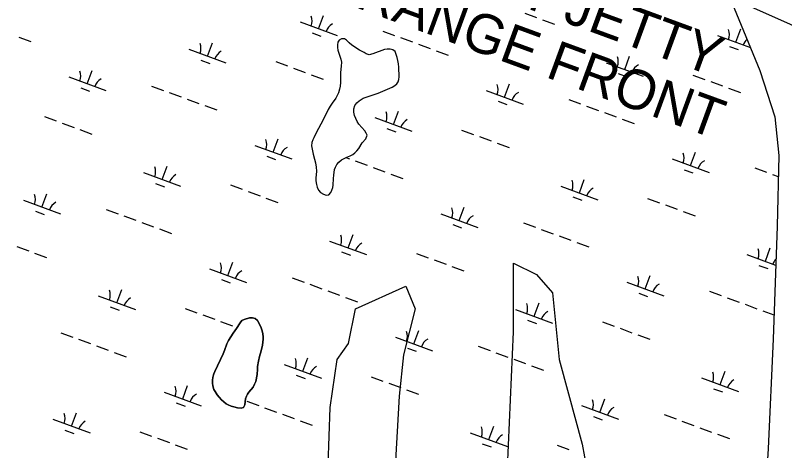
# Model space of a CAD drawing. Extents: x 3972907 to 3994831, y 172639 to 190852.
# Drawn here: x 3981218 to 3982193, y 184468 to 185019 of the extents above; entities that cross this region are included whole.
import ezdxf

# ---------------------------------------------------------------- set-up
doc = ezdxf.new("R2010")
doc.units = 0
for name, color, linetype in [('V-CHAN-NAID', 7, 'Continuous'), ('V-RIVR-JETY', 7, 'Continuous'), ('V-RIVR-RANG', 7, 'Continuous'), ('V-SITE-VEGE', 7, 'Continuous'), ('V-TOPO-SHOR', 7, 'Continuous'), ('V-WETL-SWMP', 7, 'Continuous')]:
    doc.layers.add(name, color=color, linetype=linetype)

msp = doc.modelspace()

# ---------------------------------------------------------------- linework, layer by layer
at = {"layer": 'V-RIVR-JETY'}
msp.add_spline([(3980663.75, 188142.49), (3980923.3, 187897.84), (3981219.12, 187593.73), (3981381.55, 187411.23), (3981548.76, 187223.47), (3981745.95, 186997.4), (3981995.88, 186703.14), (3982287.95, 186350.33), (3982495.82, 186079.54), (3982762.84, 185654.69), (3982971.02, 185292.43), (3983111.24, 185037.47), (3983200.02, 184881.79), (3983229.93, 184826.38)], degree=3, dxfattribs=at)
at = {"layer": 'V-RIVR-RANG'}
msp.add_lwpolyline([(3982021.28, 185087.72), (3990774.16, 181190.72)], dxfattribs=at)
at = {"layer": 'V-SITE-VEGE'}
for points in [[(3981878.15, 183971.42), (3981872.35, 184043.96), (3981854.95, 184183.23), (3981843.35, 184267.38), (3981837.55, 184360.22), (3981849.15, 184618.46), (3981849.15, 184705.5), (3981878.15, 184691), (3981898.45, 184667.78), (3981907.15, 184583.64), (3981918.75, 184540.12), (3981936.15, 184476.28), (3981947.75, 184412.45), (3981959.35, 184357.32), (3981973.85, 184310.9), (3981988.35, 184261.57), (3981982.55, 184252.87), (3981970.95, 184235.46), (3981965.15, 184206.44), (3981976.75, 184133.9), (3982005.75, 184078.78), (3982046.35, 184017.85)], [(3981518.56, 183893.08), (3981538.87, 184133.9), (3981562.06, 184229.65), (3981582.36, 184270.27), (3981602.66, 184325.4), (3981608.46, 184366.02), (3981614.26, 184450.17), (3981617.16, 184522.71), (3981625.86, 184583.64), (3981640.36, 184603.95), (3981649.06, 184647.47), (3981712.86, 184676.49), (3981724.46, 184647.47), (3981709.96, 184589.44), (3981704.16, 184537.22), (3981698.36, 184432.76), (3981704.16, 184345.71), (3981672.26, 184281.88), (3981663.56, 184189.03), (3981680.96, 184067.17), (3981672.26, 183948.21)]]:
    msp.add_lwpolyline(points, dxfattribs=at)
at = {"layer": 'V-TOPO-SHOR'}
msp.add_line((3981702.62, 184961.83), (3981701.66, 184965.75), dxfattribs=at)
for points in [[(3981701.66, 184965.75), (3981700.66, 184969.46), (3981699.12, 184973.17), (3981696.26, 184975.34), (3981692.97, 184976.4), (3981689.31, 184976.45), (3981685.92, 184975.82), (3981671.09, 184970.2), (3981666.37, 184969.24), (3981662.72, 184970.4), (3981660.07, 184972.05), (3981654.29, 184974.8), (3981644.28, 184981.31), (3981641.1, 184984.12), (3981637.71, 184987.57), (3981635, 184989.42), (3981631.35, 184989.52), (3981628.43, 184987.83), (3981626.74, 184985.02), (3981626.21, 184981.89), (3981626.16, 184978.34), (3981626.69, 184975), (3981630.29, 184963.77), (3981631.2, 184959.69), (3981631.04, 184954.77), (3981630.19, 184946.66), (3981630.03, 184943.64), (3981629.93, 184934.1), (3981629.51, 184929.33), (3981628.98, 184925.46), (3981627.55, 184921.18), (3981625.86, 184917.62), (3981623.95, 184914.45), (3981619.45, 184907.93), (3981617.01, 184904.11), (3981614.57, 184899.93), (3981607.58, 184885.78), (3981599.75, 184871.31), (3981596.14, 184864.26), (3981594.82, 184861.4), (3981593.76, 184858.12), (3981593.5, 184853.72), (3981595.41, 184843.33), (3981597.21, 184837.14), (3981598.27, 184832.31), (3981599.12, 184826.8), (3981599.49, 184821.72), (3981598.81, 184812.92), (3981598.91, 184809.53), (3981599.5, 184805.08), (3981600.4, 184801.48), (3981602.1, 184797.72), (3981604.58, 184795.07), (3981608.35, 184792.74), (3981611.95, 184791.63), (3981615.18, 184791.89), (3981617.94, 184794.91), (3981619.21, 184797.99), (3981620.27, 184801.11), (3981620.74, 184804.29), (3981621.11, 184812.61), (3981621.48, 184816.8), (3981622.59, 184823.9), (3981623.6, 184827.08), (3981625.35, 184830.36), (3981628, 184833.43), (3981631.23, 184836.03), (3981634.83, 184838.1), (3981637.9, 184839.53), (3981642.35, 184841.28), (3981645.48, 184843.03), (3981648.28, 184845.1), (3981650.93, 184847.75), (3981653.1, 184850.66), (3981657.55, 184857.87), (3981662.16, 184862.9), (3981663.7, 184867.25), (3981662.53, 184870.11), (3981660.73, 184872.97), (3981653.26, 184881.44), (3981651.03, 184884.83), (3981649.39, 184888.49), (3981647.85, 184892.52), (3981646.84, 184896.6), (3981646.84, 184900.57), (3981648.27, 184904.91), (3981650.92, 184908.52), (3981653.51, 184910.85), (3981656.06, 184912.7), (3981658.76, 184914.14), (3981677.62, 184920.71), (3981692.35, 184926.75), (3981695.63, 184928.29), (3981698.97, 184930.15), (3981701.35, 184932.53), (3981703.1, 184935.07), (3981704, 184938.04), (3981704.37, 184941.38), (3981703.73, 184953.46), (3981703.31, 184957.59), (3981702.62, 184961.83)], [(3981522.89, 184555.56), (3981521.2, 184552.39), (3981519.39, 184548.41), (3981514.1, 184542.37), (3981512.46, 184539.83), (3981511.03, 184537.02), (3981509.86, 184533.95), (3981509.12, 184530.02), (3981508.7, 184526.05), (3981507.32, 184522.98), (3981504.41, 184522.13), (3981499.53, 184522.44), (3981494.92, 184523.61), (3981491.74, 184524.61), (3981487.93, 184526.15), (3981485.17, 184527.58), (3981479.29, 184532.4), (3981476.27, 184535.68), (3981473.67, 184538.97), (3981471.13, 184542.83), (3981469.59, 184545.7), (3981468.27, 184550.36), (3981467.79, 184553.75), (3981467.79, 184557.19), (3981468.37, 184560.95), (3981469.59, 184565.41), (3981470.81, 184568.48), (3981481.34, 184590.73), (3981483.09, 184595.03), (3981486.06, 184603.29), (3981488.02, 184607.53), (3981494, 184616.7), (3981496.17, 184619.83), (3981498.5, 184622.79), (3981503.06, 184629.9), (3981505.23, 184632.81), (3981507.98, 184634.14), (3981514.92, 184636.1), (3981518.58, 184636.26), (3981522.13, 184635.3), (3981524.83, 184633.08), (3981527.91, 184627.52), (3981529.39, 184623.81), (3981530.82, 184619.78), (3981531.88, 184616.18), (3981532.31, 184612.1), (3981532.2, 184609.08), (3981531.78, 184605.58), (3981531.09, 184601.87), (3981529.4, 184594.46), (3981527.39, 184587.46), (3981526.12, 184581.32), (3981525.11, 184574.64), (3981524.85, 184571.41), (3981524.64, 184564.52), (3981522.89, 184555.56)]]:
    msp.add_lwpolyline(points, dxfattribs=at)
at = {"layer": 'V-WETL-SWMP'}
for p, q in [((3981602.32, 185002.04), (3981608.53, 185018.94)), ((3981863.42, 185021.8), (3981878.43, 185016.28)), ((3981578.85, 185010.67), (3981625.78, 184993.42)), ((3981885.94, 185013.52), (3981900.96, 185008)), ((3981683.62, 184999.19), (3981698.64, 184993.67)), ((3982130.8, 184985.02), (3982137.01, 185001.91)), ((3981222.72, 184991.38), (3981237.74, 184985.86)), ((3981594.03, 184996.87), (3981605.29, 184992.73)), ((3981706.15, 184990.91), (3981721.17, 184985.39)), ((3982107.33, 184993.64), (3982149.25, 184978.24)), ((3981461.54, 184967.56), (3981467.75, 184984.46)), ((3981728.68, 184982.63), (3981743.69, 184977.11)), ((3982122.5, 184979.85), (3982133.77, 184975.71)), ((3981438.08, 184976.19), (3981485.01, 184958.94)), ((3981751.2, 184974.35), (3981766.22, 184968.83)), ((3981453.25, 184962.39), (3981464.51, 184958.25)), ((3981547.96, 184960.53), (3981562.97, 184955.01)), ((3981990.02, 184950.54), (3981996.23, 184967.43)), ((3981570.48, 184952.25), (3981585.5, 184946.73)), ((3981966.56, 184959.16), (3982013.49, 184941.91)), ((3981285.92, 184941.12), (3981332.85, 184923.87)), ((3981309.39, 184932.49), (3981315.6, 184949.39)), ((3981593.01, 184943.97), (3981608.03, 184938.45)), ((3981981.73, 184945.36), (3981992.99, 184941.22)), ((3982076.44, 184943.51), (3982091.45, 184937.99)), ((3981837.87, 184915.47), (3981844.08, 184932.36)), ((3982098.96, 184935.23), (3982113.98, 184929.71)), ((3981301.09, 184927.32), (3981312.36, 184923.18)), ((3981390.69, 184929.64), (3981405.71, 184924.12)), ((3981413.22, 184921.36), (3981428.24, 184915.84)), ((3981814.4, 184924.09), (3981861.33, 184906.84)), ((3982121.49, 184926.95), (3982136.51, 184921.43)), ((3981435.74, 184913.08), (3981450.76, 184907.56)), ((3981919.17, 184912.62), (3981934.19, 184907.1)), ((3981458.27, 184904.8), (3981473.29, 184899.28)), ((3981829.57, 184910.3), (3981840.84, 184906.16)), ((3981941.7, 184904.34), (3981956.71, 184898.82)), ((3981697.09, 184880.99), (3981703.3, 184897.88)), ((3981964.22, 184896.06), (3981979.24, 184890.54)), ((3981255.03, 184890.98), (3981270.04, 184885.46)), ((3981277.55, 184882.7), (3981292.57, 184877.18)), ((3981673.63, 184889.61), (3981720.56, 184872.36)), ((3981986.75, 184887.78), (3982001.77, 184882.26)), ((3981300.08, 184874.42), (3981315.1, 184868.9)), ((3981688.8, 184875.81), (3981700.06, 184871.67)), ((3981783.5, 184873.96), (3981798.52, 184868.44)), ((3981544.94, 184845.92), (3981551.14, 184862.81)), ((3981806.03, 184865.68), (3981821.05, 184860.16)), ((3981521.47, 184854.54), (3981568.4, 184837.29)), ((3981828.56, 184857.4), (3981843.58, 184851.88)), ((3982073.41, 184828.89), (3982079.62, 184845.79)), ((3981536.64, 184840.75), (3981547.91, 184836.61)), ((3981637, 184839.11), (3981641.26, 184837.55)), ((3981648.76, 184834.79), (3981663.78, 184829.27)), ((3982049.95, 184837.52), (3982096.88, 184820.27)), ((3981404.16, 184811.44), (3981410.37, 184828.33)), ((3981671.29, 184826.51), (3981686.31, 184820.99)), ((3982065.12, 184823.72), (3982076.38, 184819.58)), ((3982154.72, 184826.04), (3982169.73, 184820.52)), ((3981380.7, 184820.06), (3981427.63, 184802.81)), ((3981693.82, 184818.23), (3981708.84, 184812.71)), ((3982177.24, 184817.76), (3982184.35, 184815.15)), ((3981395.87, 184806.26), (3981407.13, 184802.12)), ((3981490.57, 184804.41), (3981505.59, 184798.89)), ((3981932.64, 184794.41), (3981938.85, 184811.3)), ((3981513.1, 184796.13), (3981528.12, 184790.61)), ((3981909.17, 184803.03), (3981956.1, 184785.79)), ((3981228.54, 184784.99), (3981275.47, 184767.74)), ((3981252, 184776.37), (3981258.21, 184793.26)), ((3981535.63, 184787.85), (3981550.64, 184782.33)), ((3981924.35, 184789.24), (3981935.61, 184785.1)), ((3982019.05, 184787.38), (3982034.07, 184781.86)), ((3981780.48, 184759.34), (3981786.69, 184776.24)), ((3982041.58, 184779.1), (3982056.6, 184773.58)), ((3981243.71, 184771.2), (3981254.97, 184767.06)), ((3981333.31, 184773.52), (3981348.32, 184768)), ((3981355.83, 184765.24), (3981370.85, 184759.72)), ((3981757.02, 184767.97), (3981803.95, 184750.72)), ((3982064.11, 184770.82), (3982079.12, 184765.3)), ((3981378.36, 184756.96), (3981393.38, 184751.44)), ((3981861.79, 184756.49), (3981876.8, 184750.97)), ((3981400.89, 184748.68), (3981415.9, 184743.16)), ((3981772.19, 184754.17), (3981783.45, 184750.03)), ((3981884.31, 184748.21), (3981899.33, 184742.69)), ((3981639.71, 184724.86), (3981645.92, 184741.75)), ((3981906.84, 184739.93), (3981921.86, 184734.41)), ((3981220.17, 184726.58), (3981235.19, 184721.06)), ((3981616.24, 184733.48), (3981663.17, 184716.24)), ((3981929.37, 184731.65), (3981944.38, 184726.13)), ((3981242.69, 184718.3), (3981257.71, 184712.78)), ((3981631.41, 184719.69), (3981642.68, 184715.55)), ((3981726.12, 184717.83), (3981741.14, 184712.31)), ((3982144.72, 184716.46), (3982181.14, 184703.07)), ((3982168.19, 184707.83), (3982174.4, 184724.73)), ((3981487.55, 184689.79), (3981493.76, 184706.69)), ((3981748.65, 184709.55), (3981763.67, 184704.03)), ((3981464.09, 184698.42), (3981511.02, 184681.17)), ((3981771.17, 184701.27), (3981786.19, 184695.75)), ((3982159.89, 184702.66), (3982171.16, 184698.52)), ((3981568.85, 184686.94), (3981583.87, 184681.42)), ((3982016.03, 184672.77), (3982022.24, 184689.66)), ((3981479.26, 184684.62), (3981490.52, 184680.48)), ((3981591.38, 184678.66), (3981606.4, 184673.14)), ((3981992.56, 184681.39), (3982039.5, 184664.14)), ((3981346.78, 184655.31), (3981352.99, 184672.2)), ((3981613.91, 184670.38), (3981628.93, 184664.86)), ((3982007.74, 184667.6), (3982019, 184663.46)), ((3982097.33, 184669.91), (3982112.35, 184664.39)), ((3981323.31, 184663.93), (3981370.24, 184646.68)), ((3981636.43, 184662.1), (3981651.45, 184656.58)), ((3982119.86, 184661.63), (3982134.88, 184656.12)), ((3981338.48, 184650.14), (3981349.75, 184646)), ((3981433.19, 184648.28), (3981448.21, 184642.76)), ((3981875.26, 184638.28), (3981881.47, 184655.18)), ((3982142.39, 184653.36), (3982157.4, 184647.84)), ((3981455.72, 184640), (3981470.73, 184634.48)), ((3981851.79, 184646.91), (3981898.72, 184629.66)), ((3982164.91, 184645.08), (3982178.9, 184639.93)), ((3981478.24, 184631.72), (3981493.26, 184626.2)), ((3981866.96, 184633.11), (3981878.23, 184628.97)), ((3981961.67, 184631.26), (3981976.69, 184625.74)), ((3981723.1, 184603.22), (3981729.31, 184620.11)), ((3981984.19, 184622.98), (3981999.21, 184617.46)), ((3981275.92, 184617.39), (3981290.94, 184611.87)), ((3981298.45, 184609.11), (3981313.47, 184603.59)), ((3981699.63, 184611.84), (3981746.56, 184594.59)), ((3982006.72, 184614.7), (3982021.74, 184609.18)), ((3981320.98, 184600.83), (3981335.99, 184595.31)), ((3981804.4, 184600.36), (3981819.42, 184594.84)), ((3981343.5, 184592.55), (3981358.52, 184587.03)), ((3981714.81, 184598.04), (3981726.07, 184593.91)), ((3981826.93, 184592.08), (3981841.95, 184586.56)), ((3981582.32, 184568.73), (3981588.53, 184585.63)), ((3981849.46, 184583.8), (3981864.47, 184578.29)), ((3981558.86, 184577.36), (3981605.79, 184560.11)), ((3981871.98, 184575.53), (3981887, 184570.01)), ((3981574.03, 184563.56), (3981585.29, 184559.42)), ((3981668.74, 184561.71), (3981683.75, 184556.19)), ((3982087.34, 184560.33), (3982134.27, 184543.08)), ((3982110.8, 184551.71), (3982117.01, 184568.6)), ((3981430.17, 184533.67), (3981436.38, 184550.56)), ((3981691.26, 184553.43), (3981706.28, 184547.91)), ((3981406.7, 184542.29), (3981453.63, 184525.04)), ((3981713.79, 184545.15), (3981728.81, 184539.63)), ((3982102.51, 184546.54), (3982113.77, 184542.4)), ((3981958.65, 184516.64), (3981964.86, 184533.54)), ((3981421.87, 184528.49), (3981433.14, 184524.35)), ((3981511.47, 184530.81), (3981526.49, 184525.29)), ((3981534, 184522.53), (3981549.01, 184517.01)), ((3981935.18, 184525.27), (3981982.11, 184508.02)), ((3981289.39, 184499.18), (3981295.6, 184516.08)), ((3981556.52, 184514.25), (3981571.54, 184508.73)), ((3981950.35, 184511.47), (3981961.62, 184507.33)), ((3982039.95, 184513.79), (3982054.97, 184508.27)), ((3981265.93, 184507.81), (3981312.86, 184490.56)), ((3981579.05, 184505.98), (3981594.07, 184500.46)), ((3982062.48, 184505.51), (3982077.49, 184499.99)), ((3981281.1, 184494.01), (3981292.36, 184489.87)), ((3981375.81, 184492.16), (3981390.82, 184486.64)), ((3981817.87, 184482.16), (3981824.08, 184499.05)), ((3982085, 184497.23), (3982100.02, 184491.71)), ((3981398.33, 184483.88), (3981413.35, 184478.36)), ((3981794.41, 184490.78), (3981841.34, 184473.53)), ((3982107.53, 184488.95), (3982122.55, 184483.43)), ((3981420.86, 184475.6), (3981435.88, 184470.08)), ((3981809.58, 184476.99), (3981820.84, 184472.85)), ((3981904.28, 184475.13), (3981919.3, 184469.61))]:
    msp.add_line(p, q, dxfattribs=at)
for points in [[(3981942.39, 185380.79), (3982015.33, 185252.38), (3982074.7, 185148.97), (3982125.59, 185035.39), (3982161.21, 184949.36), (3982180.3, 184890.44), (3982184.98, 184841.7), (3982182.88, 184752.27), (3982177.83, 184609.42), (3982171.5, 184470.82), (3982161.79, 184311.87), (3982156.74, 184185.55), (3982155.91, 184088.07), (3982163.13, 184030)], [(3981701.66, 184965.75), (3981700.65, 184969.46), (3981699.12, 184973.17), (3981696.25, 184975.34), (3981692.97, 184976.4), (3981689.31, 184976.45), (3981685.92, 184975.82), (3981671.09, 184970.2), (3981666.37, 184969.24), (3981662.72, 184970.4), (3981660.07, 184972.05), (3981654.29, 184974.8), (3981644.28, 184981.32), (3981641.1, 184984.12), (3981637.71, 184987.57), (3981635, 184989.42), (3981631.35, 184989.52), (3981628.43, 184987.83), (3981626.74, 184985.02), (3981626.21, 184981.89), (3981626.16, 184978.34), (3981626.69, 184975.01), (3981630.29, 184963.77), (3981631.2, 184959.69), (3981631.04, 184954.77), (3981630.19, 184946.66), (3981630.03, 184943.64), (3981629.93, 184934.1), (3981629.51, 184929.33), (3981628.98, 184925.47), (3981627.55, 184921.17), (3981625.85, 184917.62), (3981623.95, 184914.45), (3981619.45, 184907.93), (3981617.01, 184904.11), (3981614.57, 184899.93), (3981607.58, 184885.78), (3981599.75, 184871.31), (3981596.14, 184864.26), (3981594.82, 184861.4), (3981593.76, 184858.12), (3981593.5, 184853.72), (3981595.41, 184843.33), (3981597.21, 184837.14), (3981598.27, 184832.31), (3981599.12, 184826.8), (3981599.49, 184821.72), (3981598.81, 184812.92), (3981598.91, 184809.53), (3981599.5, 184805.08), (3981600.4, 184801.48), (3981602.09, 184797.72), (3981604.58, 184795.07), (3981608.35, 184792.74), (3981611.95, 184791.63), (3981615.18, 184791.89), (3981617.94, 184794.91), (3981619.21, 184797.99), (3981620.27, 184801.11), (3981620.74, 184804.29), (3981621.11, 184812.61), (3981621.48, 184816.8), (3981622.59, 184823.9), (3981623.6, 184827.08), (3981625.35, 184830.36), (3981628, 184833.43), (3981631.23, 184836.03), (3981634.83, 184838.1), (3981637.9, 184839.53), (3981642.35, 184841.28), (3981645.48, 184843.03), (3981648.28, 184845.1), (3981650.93, 184847.74), (3981653.1, 184850.66), (3981657.55, 184857.87), (3981662.16, 184862.9), (3981663.7, 184867.25), (3981662.53, 184870.11), (3981660.73, 184872.97), (3981653.26, 184881.44), (3981651.03, 184884.83), (3981649.39, 184888.49), (3981647.85, 184892.52), (3981646.84, 184896.6), (3981646.84, 184900.57), (3981648.27, 184904.91), (3981650.92, 184908.52), (3981653.51, 184910.85), (3981656.06, 184912.7), (3981658.76, 184914.14), (3981677.62, 184920.71), (3981692.35, 184926.75), (3981695.63, 184928.29), (3981698.97, 184930.15), (3981701.35, 184932.53), (3981703.1, 184935.08), (3981704, 184938.04), (3981704.37, 184941.38), (3981703.73, 184953.46)], [(3981703.73, 184953.46), (3981703.31, 184957.59), (3981702.62, 184961.83), (3981701.66, 184965.75)]]:
    msp.add_lwpolyline(points, dxfattribs=at)
msp.add_lwpolyline([(3981522.89, 184555.56), (3981524.64, 184564.52), (3981524.85, 184571.41), (3981525.11, 184574.64), (3981526.12, 184581.32), (3981527.39, 184587.46), (3981529.4, 184594.46), (3981531.09, 184601.87), (3981531.78, 184605.58), (3981532.2, 184609.08), (3981532.31, 184612.1), (3981531.88, 184616.18), (3981530.82, 184619.78), (3981529.39, 184623.81), (3981527.91, 184627.52), (3981524.83, 184633.08), (3981522.13, 184635.3), (3981518.58, 184636.26), (3981514.92, 184636.1), (3981507.98, 184634.14), (3981505.23, 184632.81), (3981503.06, 184629.89), (3981498.5, 184622.79), (3981496.17, 184619.83), (3981494, 184616.7), (3981488.02, 184607.53), (3981486.06, 184603.29), (3981483.09, 184595.03), (3981481.34, 184590.74), (3981470.81, 184568.48), (3981469.59, 184565.41), (3981468.37, 184560.96), (3981467.79, 184557.19), (3981467.79, 184553.75), (3981468.27, 184550.36), (3981469.59, 184545.7), (3981471.13, 184542.84), (3981473.67, 184538.97), (3981476.27, 184535.68), (3981479.29, 184532.4), (3981485.17, 184527.58), (3981487.93, 184526.15), (3981491.74, 184524.61), (3981494.92, 184523.61), (3981499.53, 184522.44), (3981504.41, 184522.13), (3981507.32, 184522.98), (3981508.7, 184526.05), (3981509.12, 184530.02), (3981509.86, 184533.94), (3981511.03, 184537.02), (3981512.46, 184539.83), (3981514.1, 184542.37), (3981519.4, 184548.41), (3981521.2, 184552.39)], close=True, dxfattribs=at)
for centre, start, end in [((3981576.48, 185011.8), 339.04728, 20.59094), ((3981628.33, 184992.74), 119.04728, 160.59093), ((3982104.95, 184994.77), 339.04728, 20.59094), ((3982156.81, 184975.71), 132.44085, 160.59093), ((3981435.7, 184977.31), 339.04728, 20.59094), ((3981487.55, 184958.25), 119.04728, 160.59093), ((3981964.18, 184960.29), 339.04728, 20.59094), ((3982016.03, 184941.23), 119.04728, 160.59093), ((3981283.54, 184942.25), 339.04728, 20.59094), ((3981335.4, 184923.19), 119.04728, 160.59093), ((3981812.02, 184925.22), 339.04728, 20.59094), ((3981863.87, 184906.16), 119.04728, 160.59093), ((3981671.25, 184890.74), 339.04728, 20.59094), ((3981723.1, 184871.68), 119.04728, 160.59093), ((3981519.09, 184855.67), 339.04728, 20.59094), ((3981570.94, 184836.61), 119.04728, 160.59093), ((3982047.57, 184838.64), 339.04728, 20.59094), ((3982099.42, 184819.59), 119.04728, 160.59093), ((3981378.32, 184821.19), 339.04728, 20.59094), ((3981430.17, 184802.13), 119.04728, 160.59093), ((3981906.8, 184804.16), 339.04728, 20.59094), ((3981958.65, 184785.1), 119.04728, 160.59093), ((3981226.16, 184786.12), 339.04728, 20.59094), ((3981278.01, 184767.06), 119.04728, 160.59093), ((3981754.64, 184769.09), 339.04728, 20.59094), ((3981806.49, 184750.04), 119.04728, 160.59093), ((3981613.86, 184734.61), 339.04728, 20.59094), ((3981665.72, 184715.55), 119.04728, 160.59093), ((3982142.34, 184717.59), 339.04728, 20.59094), ((3982194.19, 184698.53), 136.52653, 160.59093), ((3981461.71, 184699.54), 339.04728, 20.59094), ((3981513.56, 184680.49), 119.04728, 160.59093), ((3981990.19, 184682.52), 339.04728, 20.59094), ((3982042.04, 184663.46), 119.04728, 160.59093), ((3981320.93, 184665.06), 339.04728, 20.59094), ((3981372.78, 184646), 119.04728, 160.59093), ((3981849.41, 184648.04), 339.04728, 20.59094), ((3981901.26, 184628.98), 119.04728, 160.59093), ((3981697.25, 184612.97), 339.04728, 20.59094), ((3981749.11, 184593.91), 119.04728, 160.59093), ((3981556.48, 184578.49), 339.04728, 20.59094), ((3981608.33, 184559.43), 119.04728, 160.59093), ((3982084.96, 184561.46), 339.04728, 20.59094), ((3982136.81, 184542.4), 119.04728, 160.59093), ((3981404.32, 184543.42), 339.04728, 20.59094), ((3981456.17, 184524.36), 119.04728, 160.59093), ((3981932.8, 184526.39), 339.04728, 20.59094), ((3981984.65, 184507.34), 119.04728, 160.59093), ((3981263.55, 184508.94), 339.04728, 20.59094), ((3981315.4, 184489.88), 119.04728, 160.59093), ((3981792.03, 184491.91), 339.04728, 20.59094), ((3981843.88, 184472.85), 119.04728, 160.59093)]:
    msp.add_arc(centre, 17.62, start, end, dxfattribs=at)

# ---------------------------------------------------------------- texts
at = {"layer": 'V-CHAN-NAID'}
for s, p in [('WEST JETTY', (3981711.2, 185084.69)), ('RANGE FRONT', (3981647.65, 185029.62))]:
    msp.add_text(s, height=50, rotation=339.86226, dxfattribs=at).set_placement(p)

doc.saveas('drawing.dxf')
